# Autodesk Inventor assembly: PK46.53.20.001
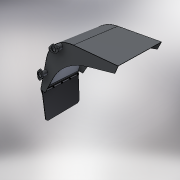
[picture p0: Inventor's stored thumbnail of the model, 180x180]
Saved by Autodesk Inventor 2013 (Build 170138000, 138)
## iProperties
Created: 2005-03
Part Number: PK46.53.20.001
Description: Крыло переднее
Document SubType Name: Assembly
Designer: tedescj
Manufacturer: Standard
Standards Organization: Custom
Author: HKostja
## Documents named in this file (12)
- C:\Product Design Suite 2013 Test Drive\Dynamic Simulation\Workspace\Assy, Chassis, Front\PK46.53.20.001.iam
- C:\Product Design Suite 2013 Test Drive\Dynamic Simulation\Workspace\Assy, Chassis, Front\PK46.53.20.001-011.ipt
- C:\Product Design Suite 2013 Test Drive\Dynamic Simulation\Workspace\Assy, Chassis, Front\PK46.53.20.002.ipt
- C:\Product Design Suite 2013 Test Drive\Dynamic Simulation\Workspace\Assy, Chassis, Front\PK46.53.20.003.ipt
- C:\Product Design Suite 2013 Test Drive\Dynamic Simulation\Workspace\Assy, Chassis, Front\PK46.53.20.007.ipt
- C:\Product Design Suite 2013 Test Drive\Dynamic Simulation\Workspace\Assy, Chassis, Front\PK46.53.20.004.ipt
- C:\Product Design Suite 2013 Test Drive\Dynamic Simulation\Workspace\Assy, Chassis, Front\PK46.53.20.005.ipt
- C:\Product Design Suite 2013 Test Drive\Dynamic Simulation\Workspace\Assy, Chassis, Front\M10-6H.5.019(S16).ipt
- C:\Product Design Suite 2013 Test Drive\Dynamic Simulation\Workspace\Assy, Chassis, Front\10.65G.019.ipt
- C:\Product Design Suite 2013 Test Drive\Dynamic Simulation\Workspace\Assy, Chassis, Front\M10-6gx30.58.019(S16).ipt
- C:\Product Design Suite 2013 Test Drive\Dynamic Simulation\Workspace\Assy, Chassis, Front\PK46.53.20.006.ipt
- C:\Product Design Suite 2013 Test Drive\Dynamic Simulation\Workspace\Assy, Chassis, Front\PK46.53.20.001.ipt
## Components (26 placed, 11 different names)
1. PK46.53.20.001:1 — Mate:8, Mate:10, Mate:9, Mate:14, Mate:15
2. PK46.53.20.001-011:1 — Mate:13, Flush:3, Mate:7, Mate:16, Mate:22, Mate:17, Mate:21
3. PK46.53.20.002:1 — Mate:13, Mate:8, Mate:10, Flush:3, Mate:9, Mate:7, Mate:20, Insert:3, Insert:20, Angle:2, Angle:1, Insert:24, Insert:23, Insert:22, Insert:21, Mate:22, Mate:23
4. PK46.53.20.003:1 — Mate:16, Mate:14, Insert:2, Tangent:1, Tangent:2
5. PK46.53.20.003:2 — Angle:1, Mate:17, Mate:15, Mate:19, Insert:1, Mate:19, Mate:20
6. PK46.53.20.007:1 — Angle:2, Insert:2
7. PK46.53.20.007:2 — Mate:19, Insert:1
8. PK46.53.20.004:1 — Insert:4, Mate:21, Insert:10, Insert:11, Insert:12, Insert:13, Insert:14
9. PK46.53.20.005:1 — Insert:4, Mate:21, Mate:20, Insert:3
10. M10-6H.5.019(S16):1 — Flush:9, Flush:8, Insert:16
11. M10-6H.5.019(S16):2 — Flush:9, Flush:10, Insert:17
12. M10-6H.5.019(S16):3 — Flush:10, Flush:11, Insert:18
13. M10-6H.5.019(S16):4 — Flush:11, Insert:19
14. M10-6H.5.019(S16):5 — Flush:8, Insert:15
15. 10.65G.019:1 — Insert:10, Insert:19
16. 10.65G.019:2 — Insert:18, Insert:11
17. 10.65G.019:3 — Insert:17, Insert:12
18. 10.65G.019:4 — Insert:15, Insert:13
19. 10.65G.019:5 — Insert:16, Insert:14
20. M10-6gx30.58.019(S16):1 — Insert:20, Flush:7
21. M10-6gx30.58.019(S16):2 — Flush:7, Flush:6, Insert:21
22. M10-6gx30.58.019(S16):3 — Flush:5, Insert:22, Flush:6
23. M10-6gx30.58.019(S16):4 — Flush:4, Insert:23, Flush:5
24. M10-6gx30.58.019(S16):5 — Insert:24, Flush:4
25. PK46.53.20.006:1 — Mate:22, Mate:19, Tangent:1, Mate:20
26. PK46.53.20.006:2 — Mate:21, Mate:22, Tangent:2, Mate:23
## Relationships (50: Mate 19, Insert 19, Flush 8, Angle 2, Tangent 2)
- Mate:13: PK46.53.20.001-011:1 ↔ PK46.53.20.002:1
- Mate:8: PK46.53.20.001:1 ↔ PK46.53.20.002:1
- Mate:10: PK46.53.20.001:1 ↔ PK46.53.20.002:1
- Flush:3 [Mate]: PK46.53.20.001-011:1 ↔ PK46.53.20.002:1
- Mate:9: PK46.53.20.001:1 ↔ PK46.53.20.002:1
- Mate:7: PK46.53.20.001-011:1 ↔ PK46.53.20.002:1
- Mate:16: PK46.53.20.001-011:1 ↔ PK46.53.20.003:1
- Mate:14: PK46.53.20.001:1 ↔ PK46.53.20.003:1
- Insert:4: PK46.53.20.004:1 ↔ PK46.53.20.005:1
- Mate:21: PK46.53.20.004:1 ↔ PK46.53.20.005:1
- Mate:20: PK46.53.20.002:1 ↔ PK46.53.20.005:1
- Insert:3: PK46.53.20.002:1 ↔ PK46.53.20.005:1
- Insert:10: PK46.53.20.004:1 ↔ 10.65G.019:1
- Insert:20: PK46.53.20.002:1 ↔ M10-6gx30.58.019(S16):1
- Mate:22: PK46.53.20.001-011:1 ↔ PK46.53.20.006:1
- Angle:2: PK46.53.20.002:1 ↔ PK46.53.20.007:1
- Insert:2: PK46.53.20.003:1 ↔ PK46.53.20.007:1
- Angle:1: PK46.53.20.002:1 ↔ PK46.53.20.003:2
- Mate:17: PK46.53.20.001-011:1 ↔ PK46.53.20.003:2
- Mate:15: PK46.53.20.001:1 ↔ PK46.53.20.003:2
- Mate:19: PK46.53.20.003:2 ↔ PK46.53.20.007:2
- Insert:1: PK46.53.20.003:2 ↔ PK46.53.20.007:2
- Insert:24: PK46.53.20.002:1 ↔ M10-6gx30.58.019(S16):5
- Flush:4: M10-6gx30.58.019(S16):4 ↔ M10-6gx30.58.019(S16):5
- Insert:23: PK46.53.20.002:1 ↔ M10-6gx30.58.019(S16):4
- Flush:5: M10-6gx30.58.019(S16):3 ↔ M10-6gx30.58.019(S16):4
- Insert:22: PK46.53.20.002:1 ↔ M10-6gx30.58.019(S16):3
- Flush:7: M10-6gx30.58.019(S16):1 ↔ M10-6gx30.58.019(S16):2
- Flush:6: M10-6gx30.58.019(S16):2 ↔ M10-6gx30.58.019(S16):3
- Insert:21: PK46.53.20.002:1 ↔ M10-6gx30.58.019(S16):2
- Flush:9: M10-6H.5.019(S16):1 ↔ M10-6H.5.019(S16):2
- Flush:10: M10-6H.5.019(S16):2 ↔ M10-6H.5.019(S16):3
- Flush:11: M10-6H.5.019(S16):3 ↔ M10-6H.5.019(S16):4
- Insert:19: M10-6H.5.019(S16):4 ↔ 10.65G.019:1
- Flush:8: M10-6H.5.019(S16):1 ↔ M10-6H.5.019(S16):5
- Insert:18: M10-6H.5.019(S16):3 ↔ 10.65G.019:2
- Insert:11: PK46.53.20.004:1 ↔ 10.65G.019:2
- Insert:17: M10-6H.5.019(S16):2 ↔ 10.65G.019:3
- Insert:12: PK46.53.20.004:1 ↔ 10.65G.019:3
- Insert:15: M10-6H.5.019(S16):5 ↔ 10.65G.019:4
- Insert:13: PK46.53.20.004:1 ↔ 10.65G.019:4
- Insert:16: M10-6H.5.019(S16):1 ↔ 10.65G.019:5
- Insert:14: PK46.53.20.004:1 ↔ 10.65G.019:5
- Mate:19: PK46.53.20.003:2 ↔ PK46.53.20.006:1
- Tangent:1: PK46.53.20.003:1 ↔ PK46.53.20.006:1
- Mate:20: PK46.53.20.003:2 ↔ PK46.53.20.006:1
- Mate:21: PK46.53.20.001-011:1 ↔ PK46.53.20.006:2
- Mate:22: PK46.53.20.002:1 ↔ PK46.53.20.006:2
- Tangent:2: PK46.53.20.003:1 ↔ PK46.53.20.006:2
- Mate:23: PK46.53.20.002:1 ↔ PK46.53.20.006:2
